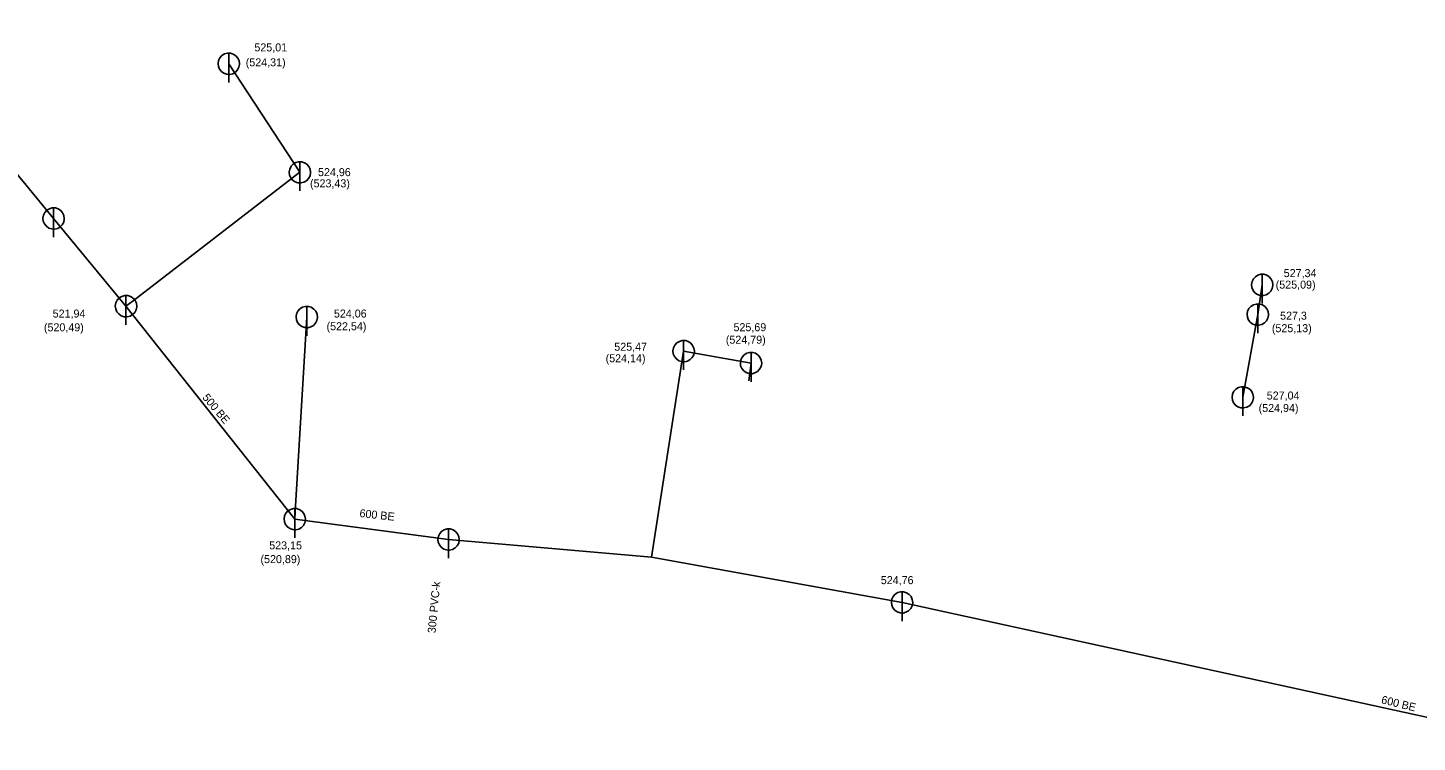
# Model space of a CAD drawing. Extents: x -476058 to -471893, y -1155786 to -1152000.
# Drawn here: x -473632.5 to -473502.4, y -1153994.8 to -1153927.9 of the extents above; entities that cross this region are included whole.
import ezdxf

# ---------------------------------------------------------------- set-up
doc = ezdxf.new("R2010")
doc.units = 0
for name, color, linetype in [('Vrstva 10', 7, 'Continuous'), ('Vrstva 18', 7, 'Continuous'), ('Vrstva 19', 7, 'Continuous'), ('Vrstva 3', 7, 'Continuous'), ('Vrstva 4', 7, 'Continuous'), ('Vrstva 45', 7, 'Continuous'), ('Vrstva 46', 7, 'Continuous'), ('Vrstva 50', 7, 'Continuous')]:
    doc.layers.add(name, color=color, linetype=linetype)

msp = doc.modelspace()

# ---------------------------------------------------------------- linework, layer by layer
at = {"layer": 'Vrstva 10'}
for p, q in [((-473613.7, -1153930.23), (-473613.7, -1153932.98)), ((-473607.04, -1153940.4), (-473607.04, -1153943.15)), ((-473630.11, -1153944.73), (-473630.11, -1153947.48)), ((-473516.87, -1153950.95), (-473516.87, -1153953.7)), ((-473623.33, -1153952.94), (-473623.33, -1153955.69)), ((-473517.29, -1153953.73), (-473517.29, -1153956.48)), ((-473606.39, -1153953.96), (-473606.39, -1153956.71)), ((-473571.08, -1153957.16), (-473571.08, -1153959.91)), ((-473564.77, -1153958.27), (-473564.77, -1153961.02)), ((-473518.7, -1153961.48), (-473518.7, -1153964.23)), ((-473607.52, -1153972.9), (-473607.52, -1153975.65)), ((-473593.11, -1153974.8), (-473593.11, -1153977.55)), ((-473550.62, -1153980.7), (-473550.62, -1153983.45))]:
    msp.add_line(p, q, dxfattribs=at)
for points in [[(-473612.7, -1153931.23), (-473612.74, -1153930.95), (-473612.86, -1153930.69), (-473613.04, -1153930.48), (-473613.28, -1153930.32), (-473613.54, -1153930.24), (-473613.83, -1153930.24), (-473614.1, -1153930.31), (-473614.34, -1153930.46), (-473614.53, -1153930.67), (-473614.65, -1153930.92), (-473614.7, -1153931.2), (-473614.67, -1153931.48), (-473614.56, -1153931.74), (-473614.38, -1153931.96), (-473614.15, -1153932.12), (-473613.88, -1153932.21), (-473613.6, -1153932.23), (-473613.33, -1153932.16), (-473613.08, -1153932.02), (-473612.89, -1153931.81), (-473612.76, -1153931.56), (-473612.7, -1153931.29), (-473612.7, -1153931.23)], [(-473606.04, -1153941.4), (-473606.08, -1153941.12), (-473606.19, -1153940.87), (-473606.38, -1153940.65), (-473606.61, -1153940.5), (-473606.88, -1153940.42), (-473607.16, -1153940.41), (-473607.43, -1153940.49), (-473607.67, -1153940.64), (-473607.86, -1153940.84), (-473607.99, -1153941.1), (-473608.04, -1153941.38), (-473608, -1153941.66), (-473607.9, -1153941.92), (-473607.72, -1153942.14), (-473607.49, -1153942.3), (-473607.22, -1153942.39), (-473606.94, -1153942.4), (-473606.66, -1153942.33), (-473606.42, -1153942.19), (-473606.22, -1153941.99), (-473606.09, -1153941.74), (-473606.04, -1153941.46), (-473606.04, -1153941.4)], [(-473629.11, -1153945.73), (-473629.15, -1153945.45), (-473629.27, -1153945.19), (-473629.45, -1153944.98), (-473629.68, -1153944.82), (-473629.95, -1153944.74), (-473630.24, -1153944.74), (-473630.51, -1153944.81), (-473630.75, -1153944.96), (-473630.94, -1153945.17), (-473631.06, -1153945.42), (-473631.11, -1153945.7), (-473631.08, -1153945.98), (-473630.97, -1153946.24), (-473630.79, -1153946.46), (-473630.56, -1153946.62), (-473630.29, -1153946.71), (-473630.01, -1153946.73), (-473629.73, -1153946.66), (-473629.49, -1153946.52), (-473629.3, -1153946.31), (-473629.17, -1153946.06), (-473629.11, -1153945.78), (-473629.11, -1153945.73)], [(-473515.87, -1153951.95), (-473515.91, -1153951.67), (-473516.03, -1153951.41), (-473516.21, -1153951.2), (-473516.45, -1153951.04), (-473516.72, -1153950.96), (-473517, -1153950.96), (-473517.27, -1153951.03), (-473517.51, -1153951.18), (-473517.7, -1153951.39), (-473517.82, -1153951.64), (-473517.87, -1153951.92), (-473517.84, -1153952.2), (-473517.73, -1153952.46), (-473517.55, -1153952.68), (-473517.32, -1153952.84), (-473517.05, -1153952.93), (-473516.77, -1153952.95), (-473516.5, -1153952.88), (-473516.25, -1153952.74), (-473516.06, -1153952.53), (-473515.93, -1153952.28), (-473515.87, -1153952.01), (-473515.87, -1153951.95)], [(-473622.33, -1153953.94), (-473622.36, -1153953.66), (-473622.48, -1153953.41), (-473622.66, -1153953.19), (-473622.9, -1153953.04), (-473623.17, -1153952.95), (-473623.45, -1153952.95), (-473623.72, -1153953.03), (-473623.96, -1153953.17), (-473624.15, -1153953.38), (-473624.28, -1153953.64), (-473624.33, -1153953.91), (-473624.29, -1153954.2), (-473624.18, -1153954.46), (-473624.01, -1153954.67), (-473623.78, -1153954.84), (-473623.51, -1153954.93), (-473623.23, -1153954.94), (-473622.95, -1153954.87), (-473622.71, -1153954.73), (-473622.51, -1153954.53), (-473622.38, -1153954.28), (-473622.33, -1153954), (-473622.33, -1153953.94)], [(-473516.29, -1153954.73), (-473516.33, -1153954.45), (-473516.45, -1153954.19), (-473516.63, -1153953.98), (-473516.86, -1153953.82), (-473517.14, -1153953.74), (-473517.42, -1153953.74), (-473517.69, -1153953.81), (-473517.93, -1153953.96), (-473518.12, -1153954.17), (-473518.24, -1153954.42), (-473518.29, -1153954.7), (-473518.26, -1153954.98), (-473518.15, -1153955.24), (-473517.97, -1153955.46), (-473517.74, -1153955.62), (-473517.47, -1153955.71), (-473517.19, -1153955.73), (-473516.92, -1153955.66), (-473516.67, -1153955.52), (-473516.48, -1153955.31), (-473516.35, -1153955.06), (-473516.29, -1153954.79), (-473516.29, -1153954.73)], [(-473605.39, -1153954.96), (-473605.43, -1153954.68), (-473605.55, -1153954.42), (-473605.73, -1153954.21), (-473605.97, -1153954.05), (-473606.23, -1153953.97), (-473606.52, -1153953.97), (-473606.79, -1153954.04), (-473607.03, -1153954.19), (-473607.22, -1153954.4), (-473607.34, -1153954.65), (-473607.39, -1153954.93), (-473607.36, -1153955.21), (-473607.25, -1153955.47), (-473607.07, -1153955.69), (-473606.84, -1153955.85), (-473606.57, -1153955.94), (-473606.29, -1153955.96), (-473606.02, -1153955.89), (-473605.77, -1153955.75), (-473605.58, -1153955.54), (-473605.45, -1153955.29), (-473605.39, -1153955.02), (-473605.39, -1153954.96)], [(-473570.08, -1153958.16), (-473570.12, -1153957.88), (-473570.24, -1153957.62), (-473570.42, -1153957.41), (-473570.66, -1153957.26), (-473570.92, -1153957.17), (-473571.21, -1153957.17), (-473571.48, -1153957.24), (-473571.72, -1153957.39), (-473571.91, -1153957.6), (-473572.03, -1153957.85), (-473572.08, -1153958.13), (-473572.05, -1153958.41), (-473571.94, -1153958.67), (-473571.76, -1153958.89), (-473571.53, -1153959.05), (-473571.26, -1153959.14), (-473570.98, -1153959.16), (-473570.71, -1153959.09), (-473570.46, -1153958.95), (-473570.27, -1153958.74), (-473570.14, -1153958.49), (-473570.08, -1153958.22), (-473570.08, -1153958.16)], [(-473563.77, -1153959.27), (-473563.81, -1153958.99), (-473563.93, -1153958.73), (-473564.11, -1153958.52), (-473564.35, -1153958.36), (-473564.61, -1153958.28), (-473564.9, -1153958.28), (-473565.17, -1153958.35), (-473565.41, -1153958.5), (-473565.6, -1153958.71), (-473565.72, -1153958.96), (-473565.77, -1153959.24), (-473565.74, -1153959.52), (-473565.63, -1153959.78), (-473565.45, -1153960), (-473565.22, -1153960.16), (-473564.95, -1153960.25), (-473564.67, -1153960.27), (-473564.4, -1153960.2), (-473564.15, -1153960.06), (-473563.96, -1153959.85), (-473563.83, -1153959.6), (-473563.77, -1153959.33), (-473563.77, -1153959.27)], [(-473517.7, -1153962.48), (-473517.74, -1153962.2), (-473517.86, -1153961.95), (-473518.04, -1153961.73), (-473518.28, -1153961.58), (-473518.54, -1153961.5), (-473518.83, -1153961.49), (-473519.1, -1153961.57), (-473519.34, -1153961.71), (-473519.53, -1153961.92), (-473519.65, -1153962.18), (-473519.7, -1153962.46), (-473519.67, -1153962.74), (-473519.56, -1153963), (-473519.38, -1153963.22), (-473519.15, -1153963.38), (-473518.88, -1153963.47), (-473518.6, -1153963.48), (-473518.33, -1153963.41), (-473518.08, -1153963.27), (-473517.89, -1153963.07), (-473517.76, -1153962.82), (-473517.7, -1153962.54), (-473517.7, -1153962.48)], [(-473606.52, -1153973.9), (-473606.56, -1153973.62), (-473606.68, -1153973.36), (-473606.86, -1153973.15), (-473607.1, -1153973), (-473607.36, -1153972.91), (-473607.65, -1153972.91), (-473607.92, -1153972.98), (-473608.16, -1153973.13), (-473608.35, -1153973.34), (-473608.47, -1153973.59), (-473608.52, -1153973.87), (-473608.49, -1153974.15), (-473608.38, -1153974.41), (-473608.2, -1153974.63), (-473607.97, -1153974.79), (-473607.7, -1153974.88), (-473607.42, -1153974.9), (-473607.15, -1153974.83), (-473606.9, -1153974.69), (-473606.71, -1153974.48), (-473606.58, -1153974.23), (-473606.52, -1153973.96), (-473606.52, -1153973.9)], [(-473592.11, -1153975.8), (-473592.15, -1153975.53), (-473592.26, -1153975.27), (-473592.45, -1153975.05), (-473592.68, -1153974.9), (-473592.95, -1153974.82), (-473593.23, -1153974.81), (-473593.51, -1153974.89), (-473593.74, -1153975.04), (-473593.93, -1153975.25), (-473594.06, -1153975.5), (-473594.11, -1153975.78), (-473594.07, -1153976.06), (-473593.97, -1153976.32), (-473593.79, -1153976.54), (-473593.56, -1153976.7), (-473593.29, -1153976.79), (-473593.01, -1153976.8), (-473592.73, -1153976.73), (-473592.49, -1153976.59), (-473592.29, -1153976.39), (-473592.16, -1153976.14), (-473592.11, -1153975.86), (-473592.11, -1153975.8)], [(-473549.62, -1153981.7), (-473549.66, -1153981.42), (-473549.78, -1153981.16), (-473549.96, -1153980.95), (-473550.2, -1153980.79), (-473550.47, -1153980.71), (-473550.75, -1153980.71), (-473551.02, -1153980.78), (-473551.26, -1153980.93), (-473551.45, -1153981.14), (-473551.57, -1153981.39), (-473551.62, -1153981.67), (-473551.59, -1153981.95), (-473551.48, -1153982.21), (-473551.3, -1153982.43), (-473551.07, -1153982.59), (-473550.8, -1153982.68), (-473550.52, -1153982.7), (-473550.25, -1153982.63), (-473550, -1153982.49), (-473549.81, -1153982.28), (-473549.68, -1153982.03), (-473549.62, -1153981.76), (-473549.62, -1153981.7)]]:
    msp.add_lwpolyline(points, dxfattribs=at)
at = {"layer": 'Vrstva 45'}
for points in [[(-473630.11, -1153945.73), (-473656.5, -1153913.55)], [(-473623.33, -1153953.94), (-473630.11, -1153945.73)], [(-473607.52, -1153973.9), (-473623.33, -1153953.94)], [(-473593.11, -1153975.8), (-473607.52, -1153973.9)], [(-473574.08, -1153977.47), (-473593.11, -1153975.8)], [(-473550.62, -1153981.7), (-473574.08, -1153977.47)]]:
    msp.add_lwpolyline(points, dxfattribs=at)
at = {"layer": 'Vrstva 46'}
for points in [[(-473525.18, -1153987.27), (-473550.62, -1153981.7)], [(-473490.77, -1153994.8), (-473525.18, -1153987.27)]]:
    msp.add_lwpolyline(points, dxfattribs=at)
at = {"layer": 'Vrstva 50'}
for points in [[(-473613.7, -1153931.23), (-473607.04, -1153941.4), (-473622.67, -1153953.44), (-473623.33, -1153953.94)], [(-473516.87, -1153951.95), (-473517.29, -1153954.73), (-473518.7, -1153962.48)], [(-473606.39, -1153954.96), (-473607.48, -1153973.18), (-473607.52, -1153973.9)], [(-473571.08, -1153958.16), (-473574.08, -1153977.47)], [(-473571.08, -1153958.16), (-473564.77, -1153959.27), (-473564.98, -1153960.94)]]:
    msp.add_lwpolyline(points, dxfattribs=at)

# ---------------------------------------------------------------- texts
at = {"layer": 'Vrstva 18'}
for s, rotation, p in [('500 BE', 310.1222, (-473616.22, -1153962.53)), ('600 BE', 353.9044, (-473601.48, -1153973.7)), ('600 BE', 346.3543, (-473505.77, -1153991.15))]:
    msp.add_text(s, height=0.75, rotation=rotation, dxfattribs=at).set_placement(p)
at = {"layer": 'Vrstva 19'}
msp.add_text('300 PVC-k', height=0.75, rotation=84.6182, dxfattribs=at).set_placement((-473594.33, -1153984.61))
at = {"layer": 'Vrstva 3'}
for s, p in [('525,01', (-473611.3, -1153930.07)), ('524,96', (-473605.34, -1153941.76)), ('527,34', (-473514.86, -1153951.22)), ('521,94', (-473630.2, -1153955.01)), ('524,06', (-473603.85, -1153955.01)), ('527,3', (-473515.2, -1153955.21)), ('525,69', (-473566.41, -1153956.29)), ('525,47', (-473577.58, -1153958.12)), ('527,04', (-473516.45, -1153962.69)), ('523,15', (-473609.91, -1153976.73)), ('524,76', (-473552.61, -1153979.99))]:
    msp.add_text(s, height=0.75, dxfattribs=at).set_placement(p)
at = {"layer": 'Vrstva 4'}
for s, p in [('(524,31)', (-473612.11, -1153931.47)), ('(523,43)', (-473606.09, -1153942.81)), ('(525,09)', (-473515.61, -1153952.3)), ('(520,49)', (-473631.02, -1153956.3)), ('(522,54)', (-473604.54, -1153956.2)), ('(525,13)', (-473515.97, -1153956.38)), ('(524,79)', (-473567.13, -1153957.46)), ('(524,14)', (-473578.39, -1153959.2)), ('(524,94)', (-473517.21, -1153963.86)), ('(520,89)', (-473610.73, -1153978.02))]:
    msp.add_text(s, height=0.75, dxfattribs=at).set_placement(p)

doc.saveas('drawing.dxf')
